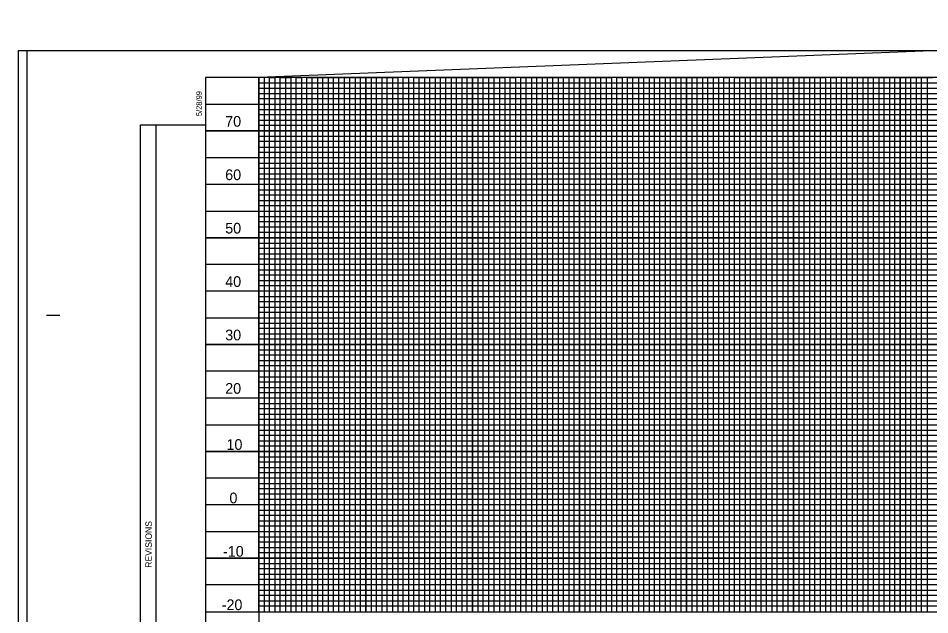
# Model space of a CAD drawing. Extents: x 1637092 to 1638792, y 884647 to 885778.
# Drawn here: x 1637092 to 1637944, y 885219 to 885778 of the extents above; entities that cross this region are included whole.
import ezdxf

# ---------------------------------------------------------------- set-up
doc = ezdxf.new("R2010")
doc.units = 0
for name, color, linetype in [('Exist Vertical Profile Vertical Axis Label', 7, 'Continuous'), ('Prop VPI Label', 7, 'Continuous'), ('Scratch_Level_3', 7, 'Continuous'), ('Sheet Block Revision CELL', 7, 'Continuous'), ('Sheet Cutting Line CELL', 7, 'Continuous'), ('Sheet DOT Grid CELL', 7, 'Continuous'), ('Sheet Layout Profile Border Port 1', 7, 'Continuous'), ('Sheet Plan And Profile CELL', 7, 'Continuous'), ('Sheet Profile CELL', 7, 'Continuous'), ('Sheet Profile Grid Major CELL', 7, 'Continuous'), ('Sheet Profile Grid Middle CELL', 7, 'Continuous'), ('Sheet Profile Grid Minor CELL', 7, 'Continuous'), ('Stewart Plot Border Xerox6279 and LJ5000', 7, 'Continuous')]:
    doc.layers.add(name, color=color, linetype=linetype)

msp = doc.modelspace()

# ---------------------------------------------------------------- linework, layer by layer
at = {"layer": 'Prop VPI Label'}
msp.add_lwpolyline([(1637416.66, 885297.14), (1637566.66, 885297.14), (1637566.66, 885247.14), (1637416.66, 885247.14)], close=True, dxfattribs=at)
at = {"layer": 'Scratch_Level_3'}
msp.add_lwpolyline([(1637316.66, 885722.14), (1637316.66, 884697.14), (1638716.66, 884697.14), (1638716.66, 885777.71)], close=True, dxfattribs=at)
at = {"layer": 'Sheet Block Revision CELL'}
msp.add_line((1637220.66, 884887.14), (1637220.66, 885677.79), dxfattribs=at)
msp.add_lwpolyline([(1637206.11, 884887.14), (1637206.11, 885677.79), (1637266.66, 885677.79), (1637266.66, 884887.14)], close=True, dxfattribs=at)
at = {"layer": 'Sheet Cutting Line CELL'}
for p, q in [((1638783.66, 885747.14), (1637099.66, 885747.14)), ((1637099.66, 885747.14), (1637099.66, 884647.14))]:
    msp.add_line(p, q, dxfattribs=at)
at = {"layer": 'Sheet DOT Grid CELL'}
for p, q in [((1637316.66, 885222.14), (1637316.66, 885722.14)), ((1637366.66, 885222.14), (1637366.66, 885722.14)), ((1637416.66, 885222.14), (1637416.66, 885722.14)), ((1637466.66, 885222.14), (1637466.66, 885722.14)), ((1637516.66, 885222.14), (1637516.66, 885722.14)), ((1637566.66, 885222.14), (1637566.66, 885722.14)), ((1637616.66, 885222.14), (1637616.66, 885722.14)), ((1637666.66, 885222.14), (1637666.66, 885722.14)), ((1637716.66, 885222.14), (1637716.66, 885722.14)), ((1637766.66, 885222.14), (1637766.66, 885722.14)), ((1637816.66, 885222.14), (1637816.66, 885722.14)), ((1637866.66, 885222.14), (1637866.66, 885722.14)), ((1637916.66, 885222.14), (1637916.66, 885722.14)), ((1638566.61, 885672.14), (1637266.66, 885672.14)), ((1638566.61, 885622.14), (1637266.66, 885622.14)), ((1638566.61, 885572.14), (1637266.66, 885572.14)), ((1638566.62, 885522.14), (1637266.66, 885522.14)), ((1638766.66, 885472.14), (1637266.66, 885472.14)), ((1638766.66, 885422.14), (1637266.66, 885422.14)), ((1638766.66, 885372.14), (1637266.66, 885372.14)), ((1638766.66, 885322.14), (1637266.66, 885322.14)), ((1638766.66, 885272.14), (1637266.66, 885272.14))]:
    msp.add_line(p, q, dxfattribs=at)
at = {"layer": 'Sheet Layout Profile Border Port 1'}
msp.add_lwpolyline([(1637316.66, 885561.09), (1637316.66, 885222.14), (1638716.66, 885222.14), (1638716.66, 885521.09)], dxfattribs=at)
at = {"layer": 'Sheet Plan And Profile CELL'}
msp.add_line((1637118.16, 885499.64), (1637130.66, 885499.64), dxfattribs=at)
msp.add_lwpolyline([(1638766.66, 885722.14), (1637266.66, 885722.14), (1637266.66, 884672.14), (1638766.66, 884672.14)], close=True, dxfattribs=at)
at = {"layer": 'Sheet Profile CELL'}
for p, q in [((1637118.16, 885499.64), (1637130.66, 885499.64)), ((1637266.66, 885222.14), (1638766.66, 885222.14))]:
    msp.add_line(p, q, dxfattribs=at)
msp.add_lwpolyline([(1638766.66, 885722.14), (1637266.66, 885722.14), (1637266.66, 884672.14), (1638766.66, 884672.14)], close=True, dxfattribs=at)
at = {"layer": 'Sheet Profile Grid Major CELL'}
for p, q in [((1637766.66, 885222.14), (1637816.66, 885222.14)), ((1637866.66, 885222.14), (1637916.66, 885222.14))]:
    msp.add_line(p, q, dxfattribs=at)
for points in [[(1637316.66, 885722.14), (1637316.66, 885222.14), (1637366.66, 885222.14), (1637366.66, 885722.14), (1637416.66, 885722.14), (1637416.66, 885222.14), (1637466.66, 885222.14), (1637466.66, 885722.14), (1637516.66, 885722.14), (1637516.66, 885222.14), (1637566.66, 885222.14), (1637566.66, 885722.14), (1637616.66, 885722.14), (1637616.66, 885222.14), (1637666.66, 885222.14), (1637666.66, 885722.14), (1637716.66, 885722.14), (1637716.66, 885222.14), (1637766.66, 885222.14), (1637766.66, 885722.14), (1637816.66, 885722.14), (1637816.66, 885222.14), (1637866.66, 885222.14), (1637866.66, 885722.14), (1637916.66, 885722.14), (1637916.66, 885222.14), (1637966.66, 885222.14)], [(1637266.66, 885672.14), (1638566.66, 885672.14)], [(1638566.66, 885622.14), (1637266.66, 885622.14), (1637266.66, 885572.14), (1638566.61, 885572.14)], [(1638566.62, 885522.14), (1637266.66, 885522.14), (1637266.66, 885472.14), (1638766.66, 885472.14)], [(1638766.66, 885422.14), (1637266.66, 885422.14), (1637266.66, 885372.14), (1638766.66, 885372.14)], [(1638766.66, 885322.14), (1637266.66, 885322.14), (1637266.66, 885322.14), (1637266.66, 885272.14), (1638766.66, 885272.14)]]:
    msp.add_lwpolyline(points, dxfattribs=at)
at = {"layer": 'Sheet Profile Grid Middle CELL'}
msp.add_line((1637266.66, 885697.14), (1638566.61, 885697.14), dxfattribs=at)
for points in [[(1637341.66, 885722.14), (1637341.66, 885222.14), (1637391.66, 885222.14), (1637391.66, 885722.14), (1637441.66, 885722.14), (1637441.66, 885222.14), (1637491.66, 885222.14), (1637491.66, 885722.14), (1637541.66, 885722.14), (1637541.66, 885222.14), (1637591.66, 885222.14), (1637591.66, 885722.14), (1637641.66, 885722.14), (1637641.66, 885222.14), (1637691.66, 885222.14), (1637691.66, 885722.14), (1637741.66, 885722.14), (1637741.66, 885222.14), (1637791.66, 885222.14), (1637791.66, 885722.14), (1637841.66, 885722.14), (1637841.66, 885222.14), (1637891.66, 885222.14), (1637891.66, 885222.14), (1637891.66, 885722.14), (1637941.66, 885722.14), (1637941.66, 885222.14), (1637991.66, 885222.14)], [(1638566.66, 885647.14), (1637266.66, 885647.14), (1637266.66, 885597.14), (1638566.66, 885597.14)], [(1638566.61, 885547.14), (1637266.66, 885547.14), (1637266.66, 885497.14), (1638591.66, 885497.14)], [(1638766.66, 885447.14), (1637266.66, 885447.14), (1637266.66, 885397.14), (1638766.66, 885397.14)], [(1638766.66, 885347.14), (1637266.66, 885347.14), (1637266.66, 885297.14), (1638766.66, 885297.14)], [(1638766.66, 885247.14), (1637266.66, 885247.14)]]:
    msp.add_lwpolyline(points, dxfattribs=at)
at = {"layer": 'Sheet Profile Grid Minor CELL'}
for p, q in [((1637316.66, 885717.14), (1638566.66, 885717.14)), ((1637316.66, 885712.14), (1637316.66, 885712.14)), ((1638566.66, 885712.14), (1637316.66, 885711.79)), ((1637316.66, 885707.14), (1638566.66, 885707.14)), ((1638566.61, 885587.14), (1637316.66, 885587.14)), ((1638566.66, 885582.14), (1637316.66, 885582.14)), ((1638566.66, 885577.14), (1637316.66, 885577.14)), ((1637316.66, 885567.14), (1638566.61, 885567.14)), ((1638566.61, 885562.14), (1637316.66, 885562.14)), ((1637316.66, 885557.14), (1638566.61, 885557.14)), ((1638566.62, 885537.14), (1637316.66, 885537.14)), ((1637316.66, 885532.14), (1638566.62, 885532.14)), ((1638716.66, 885512.14), (1637316.66, 885512.14)), ((1637316.66, 885507.14), (1638716.66, 885507.14)), ((1638716.66, 885487.14), (1637316.66, 885487.14)), ((1637316.66, 885482.14), (1638716.66, 885482.14)), ((1638716.66, 885477.14), (1637316.66, 885477.14)), ((1637316.66, 885467.14), (1638716.66, 885467.14)), ((1638716.66, 885462.14), (1637316.66, 885462.14)), ((1637316.66, 885457.14), (1638716.66, 885457.14)), ((1638716.66, 885452.14), (1637316.66, 885452.14)), ((1637316.66, 885442.14), (1638716.66, 885442.14)), ((1638716.66, 885437.14), (1637316.66, 885437.14)), ((1637316.66, 885432.14), (1638716.66, 885432.14)), ((1638716.66, 885427.14), (1637316.66, 885427.14)), ((1637316.66, 885417.14), (1638716.66, 885417.14)), ((1638716.66, 885412.14), (1637316.66, 885412.14)), ((1637316.66, 885407.14), (1638716.66, 885407.14)), ((1638716.66, 885402.14), (1637316.66, 885402.14)), ((1637316.66, 885392.14), (1638716.66, 885392.14)), ((1638716.66, 885387.14), (1637316.66, 885387.14)), ((1637316.66, 885382.14), (1638716.66, 885382.14)), ((1638716.66, 885377.14), (1637316.66, 885377.14)), ((1637316.66, 885367.14), (1638716.66, 885367.14)), ((1638716.66, 885362.14), (1637316.66, 885362.14)), ((1637316.66, 885357.14), (1638716.66, 885357.14)), ((1638716.66, 885352.14), (1637316.66, 885352.14)), ((1637316.66, 885342.14), (1638716.66, 885342.14)), ((1638716.66, 885337.14), (1637316.66, 885337.14)), ((1638716.66, 885332.14), (1637316.66, 885332.14)), ((1638716.66, 885327.14), (1637316.66, 885327.14)), ((1637316.66, 885317.14), (1638716.66, 885317.14)), ((1638716.66, 885312.14), (1637316.66, 885312.14)), ((1637316.66, 885307.14), (1638716.66, 885307.14)), ((1638716.66, 885302.14), (1637316.66, 885302.14)), ((1637316.66, 885292.14), (1638716.66, 885292.14)), ((1638716.66, 885287.14), (1637316.66, 885287.14)), ((1637316.66, 885282.14), (1638716.66, 885282.14)), ((1638716.66, 885277.14), (1637316.66, 885277.14)), ((1637316.66, 885267.14), (1638716.66, 885267.14)), ((1638716.66, 885262.14), (1637316.66, 885262.14)), ((1637316.66, 885257.14), (1638716.66, 885257.14)), ((1638716.66, 885252.14), (1637316.66, 885252.14)), ((1637316.66, 885242.14), (1638716.66, 885242.14)), ((1638716.66, 885237.14), (1637316.66, 885237.14)), ((1637316.66, 885232.14), (1638716.66, 885232.14))]:
    msp.add_line(p, q, dxfattribs=at)
for points in [[(1637321.66, 885722.14), (1637321.66, 885222.14), (1637326.66, 885222.14), (1637326.66, 885722.14), (1637331.66, 885722.14), (1637331.66, 885222.14), (1637336.66, 885222.14), (1637336.66, 885722.14), (1637346.66, 885722.14), (1637346.66, 885222.14), (1637351.66, 885222.14), (1637351.66, 885722.14), (1637356.66, 885722.14), (1637356.66, 885222.14), (1637361.66, 885222.14), (1637371.66, 885222.14), (1637376.66, 885222.14), (1637376.66, 885722.14), (1637381.66, 885722.14), (1637381.66, 885222.14), (1637386.66, 885222.14), (1637386.66, 885722.14), (1637396.66, 885722.14), (1637396.66, 885222.14), (1637401.66, 885222.14), (1637401.66, 885722.14), (1637406.66, 885722.14), (1637406.66, 885222.14), (1637411.66, 885222.14), (1637411.66, 885722.14), (1637421.66, 885722.14), (1637421.66, 885222.14), (1637426.66, 885222.14), (1637426.66, 885722.14), (1637431.66, 885722.14), (1637431.66, 885222.14), (1637436.66, 885222.14), (1637436.66, 885722.14), (1637446.66, 885722.14), (1637446.66, 885222.14), (1637451.66, 885222.14), (1637451.66, 885722.14), (1637456.66, 885722.14), (1637456.66, 885222.14), (1637461.66, 885222.14), (1637461.66, 885722.14), (1637471.66, 885722.14), (1637471.66, 885222.14), (1637476.66, 885222.14), (1637476.66, 885722.14), (1637481.66, 885722.14), (1637481.66, 885222.14), (1637486.66, 885222.14), (1637486.66, 885722.14), (1637496.66, 885722.14), (1637496.66, 885222.14), (1637501.66, 885222.14), (1637501.66, 885722.14), (1637506.66, 885722.14), (1637506.66, 885222.14), (1637511.66, 885222.14), (1637511.66, 885722.14), (1637521.66, 885722.14), (1637521.66, 885222.14), (1637526.66, 885222.14), (1637526.66, 885722.14), (1637531.66, 885722.14), (1637531.66, 885222.14)], [(1637361.66, 885222.14), (1637361.66, 885722.14), (1637371.66, 885722.14), (1637371.66, 885222.14)], [(1637531.66, 885222.14), (1637536.66, 885222.14), (1637536.66, 885722.14), (1637546.66, 885722.14), (1637546.66, 885222.14), (1637551.66, 885222.14), (1637551.66, 885722.14), (1637556.66, 885722.14), (1637556.66, 885222.14), (1637561.66, 885222.14), (1637561.66, 885722.14), (1637571.66, 885722.14), (1637571.66, 885222.14), (1637576.66, 885222.14), (1637576.66, 885722.14), (1637581.66, 885722.14), (1637581.66, 885222.14), (1637586.66, 885222.14), (1637586.66, 885722.14), (1637596.66, 885722.14), (1637596.66, 885222.14), (1637601.66, 885222.14), (1637601.66, 885722.14), (1637606.66, 885722.14), (1637606.66, 885222.14), (1637611.66, 885222.14), (1637611.66, 885722.14), (1637621.66, 885722.14), (1637621.66, 885222.14), (1637626.66, 885222.14), (1637626.66, 885722.14), (1637631.66, 885722.14), (1637631.66, 885222.14), (1637636.66, 885222.14), (1637636.66, 885722.14), (1637646.66, 885722.14), (1637646.66, 885222.14), (1637651.66, 885222.14), (1637651.66, 885722.14), (1637656.66, 885722.14), (1637656.66, 885222.14), (1637661.66, 885222.14), (1637661.66, 885722.14), (1637671.66, 885722.14), (1637671.66, 885222.14), (1637676.66, 885222.14), (1637676.66, 885722.14), (1637681.66, 885722.14), (1637681.66, 885222.14), (1637686.66, 885222.14), (1637686.66, 885722.14), (1637696.66, 885722.14), (1637696.66, 885222.14), (1637701.66, 885222.14), (1637701.66, 885722.14), (1637706.66, 885722.14), (1637706.66, 885222.14), (1637711.66, 885222.14), (1637711.66, 885722.14), (1637721.66, 885722.14), (1637721.66, 885222.14), (1637726.66, 885222.14), (1637726.66, 885722.14), (1637731.66, 885722.14), (1637731.66, 885222.14), (1637736.66, 885222.14), (1637736.66, 885722.14), (1637746.66, 885722.14), (1637746.66, 885222.14), (1637751.66, 885222.14), (1637751.66, 885722.14), (1637756.66, 885722.14), (1637756.66, 885222.14), (1637761.66, 885222.14), (1637761.66, 885722.14), (1637771.66, 885722.14), (1637771.66, 885222.14), (1637776.66, 885222.14), (1637776.66, 885722.14), (1637781.66, 885722.14), (1637781.66, 885222.14), (1637786.66, 885222.14), (1637786.66, 885722.14), (1637796.66, 885722.14), (1637796.66, 885222.14), (1637801.66, 885222.14), (1637801.66, 885722.14), (1637806.66, 885722.14), (1637806.66, 885222.14), (1637811.66, 885222.14), (1637811.66, 885722.14), (1637821.66, 885722.14), (1637821.66, 885222.14), (1637826.66, 885222.14), (1637826.66, 885722.14), (1637831.66, 885722.14), (1637831.66, 885222.14), (1637836.66, 885222.14), (1637836.66, 885722.14), (1637846.66, 885722.14)], [(1637846.66, 885722.14), (1637846.66, 885222.14), (1637851.66, 885222.14), (1637851.66, 885722.14), (1637856.66, 885722.14), (1637856.66, 885222.14), (1637861.66, 885222.14), (1637861.66, 885722.14), (1637871.66, 885722.14), (1637871.66, 885222.14), (1637876.66, 885222.14), (1637876.66, 885722.14), (1637881.66, 885722.14), (1637881.66, 885222.14), (1637886.66, 885222.14), (1637886.66, 885722.14), (1637896.66, 885722.14), (1637896.66, 885222.14), (1637901.66, 885222.14), (1637901.66, 885722.14), (1637906.66, 885722.14), (1637906.66, 885222.14), (1637911.66, 885222.14), (1637911.66, 885722.14), (1637921.66, 885722.14), (1637921.66, 885222.14), (1637926.66, 885222.14), (1637926.66, 885722.14), (1637931.66, 885722.14), (1637931.66, 885222.14), (1637936.66, 885222.14), (1637936.66, 885722.14), (1637946.66, 885722.14)], [(1638566.66, 885702.14), (1637316.66, 885702.14), (1637316.66, 885692.14), (1638566.66, 885692.14)], [(1638566.61, 885687.14), (1637316.66, 885687.14), (1637316.66, 885682.14), (1638566.66, 885682.14)], [(1638566.66, 885677.14), (1637316.66, 885677.14), (1637316.66, 885667.14), (1638566.66, 885667.14)], [(1638566.66, 885662.14), (1637316.66, 885662.14), (1637316.66, 885657.14), (1638566.66, 885657.14)], [(1638566.66, 885652.14), (1637316.66, 885652.14), (1637316.66, 885642.14), (1638566.66, 885642.14)], [(1638566.66, 885637.14), (1637316.66, 885637.14), (1637316.66, 885632.14), (1638566.66, 885632.14)], [(1638566.66, 885627.14), (1637316.66, 885627.14), (1637316.66, 885617.14), (1638566.66, 885617.14)], [(1638566.66, 885612.04), (1637316.76, 885612.04), (1637316.76, 885607.14), (1638566.66, 885607.14)], [(1638566.66, 885602.14), (1637316.66, 885602.14), (1637316.66, 885592.14), (1638566.66, 885592.14)], [(1638566.61, 885552.14), (1637316.66, 885552.14), (1637316.66, 885542.14), (1638566.62, 885542.14)], [(1638566.62, 885527.14), (1637316.66, 885527.14), (1637316.66, 885517.14), (1638716.66, 885517.14)], [(1638716.66, 885502.14), (1637316.66, 885502.14), (1637316.66, 885492.14), (1638716.66, 885492.14)], [(1638716.66, 885227.14), (1637316.66, 885227.14)]]:
    msp.add_lwpolyline(points, dxfattribs=at)
at = {"layer": 'Stewart Plot Border Xerox6279 and LJ5000'}
msp.add_lwpolyline([(1637091.66, 884647.14), (1638791.66, 884647.14), (1638791.66, 885747.14), (1637091.66, 885747.14)], close=True, dxfattribs=at)

# ---------------------------------------------------------------- texts
at = {"layer": 'Exist Vertical Profile Vertical Axis Label'}
for s, p in [('70', (1637285.27, 885676.15)), ('60', (1637285.27, 885626.15)), ('50', (1637285.27, 885576.15)), ('40', (1637285.27, 885526.15)), ('30', (1637285.27, 885476.15)), ('20', (1637285.27, 885426.15)), ('10', (1637286.46, 885373.61)), ('0', (1637289.22, 885323.61)), ('-10', (1637283.19, 885273.61)), ('-20', (1637281.99, 885223.61))]:
    msp.add_text(s, height=10, dxfattribs=at).set_placement(p)
at = {"layer": 'Sheet Block Revision CELL'}
msp.add_text('REVISIONS', height=6, rotation=90, dxfattribs=at).set_placement((1637216.61, 885263.29))
at = {"layer": 'Sheet Plan And Profile CELL'}
msp.add_text('5/28/99', height=5.25, rotation=90, dxfattribs=at).set_placement((1637263.41, 885686.07))
at = {"layer": 'Sheet Profile CELL'}
msp.add_text('5/28/99', height=5.25, rotation=90, dxfattribs=at).set_placement((1637263.42, 885686.05))

doc.saveas('drawing.dxf')
